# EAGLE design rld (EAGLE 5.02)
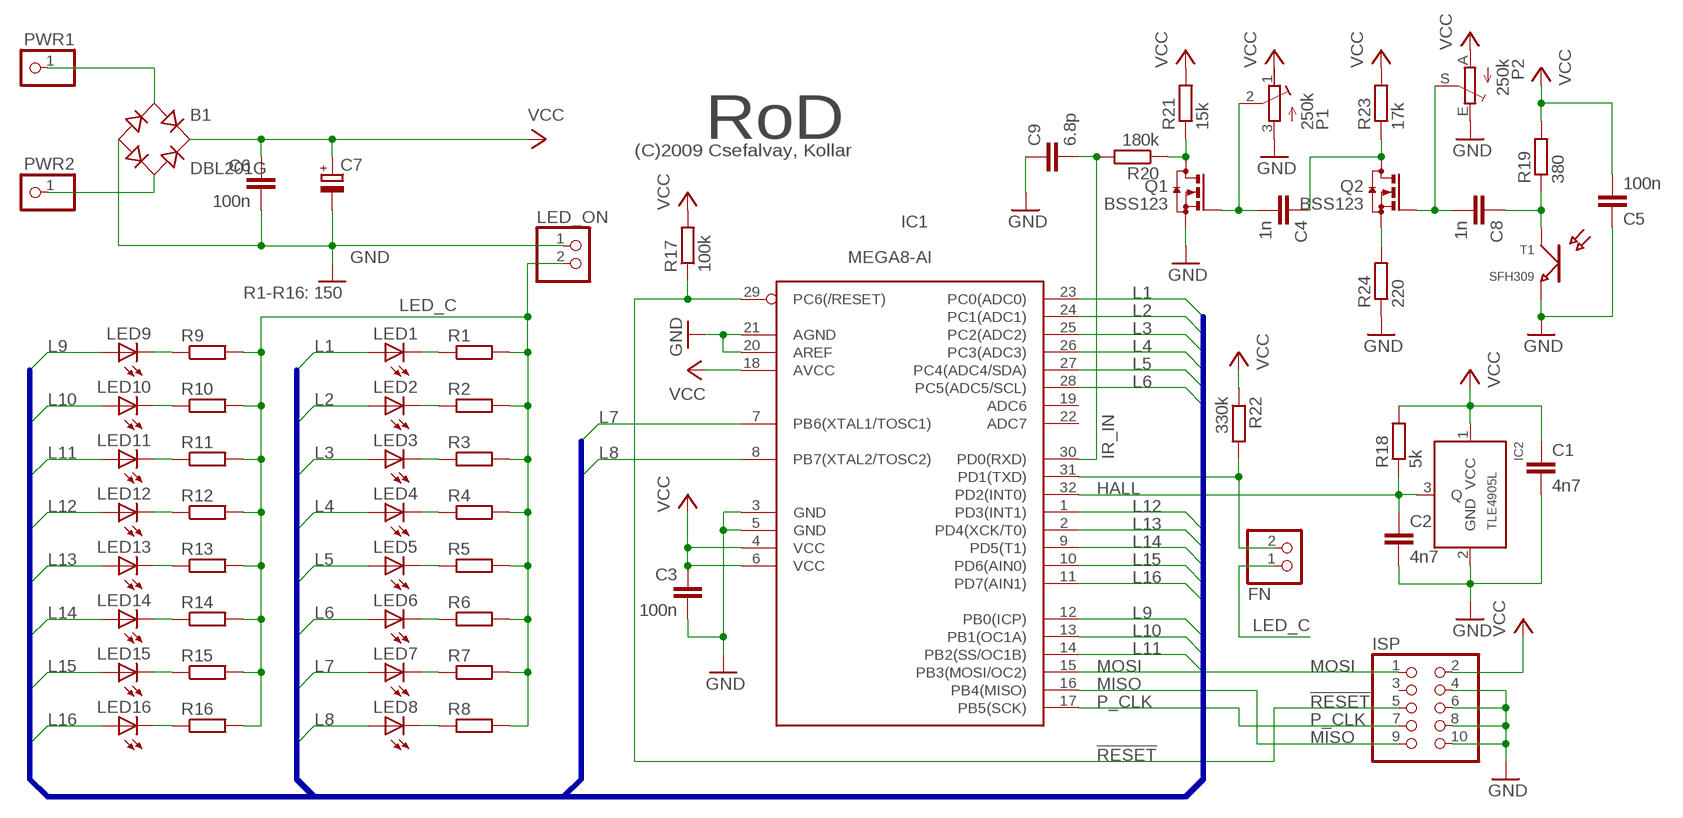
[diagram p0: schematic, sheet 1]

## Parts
B1  DBL201G  [DB]
C1  4n7  C-EUC1206  [C1206]
C2  4n7  C-EUC1206  [C1206]
C3  100n  C-EUC1206  [C1206]
C4  1n  C-EUC1206  [C1206]
C5  100n  C-EUC1206  [C1206]
C6  100n  C-EUC1206  [C1206]
C7  CPOL-EUE2.5-7  [E2,5-7]
C8  1n  C-EUC1206  [C1206]
C9  6.8p  C-EUC1206  [C1206]
FN  PINHD-1X2  [1X02]
IC1  MEGA8-AI  [TQFP32-08]
IC2  TLE4905L  [TO92-]
ISP  PINHD-2X5  [2X05]
LED1  LEDCHIPLED_1206  [CHIPLED_1206]
LED2  LEDCHIPLED_1206  [CHIPLED_1206]
LED3  LEDCHIPLED_1206  [CHIPLED_1206]
LED4  LEDCHIPLED_1206  [CHIPLED_1206]
LED5  LEDCHIPLED_1206  [CHIPLED_1206]
LED6  LEDCHIPLED_1206  [CHIPLED_1206]
LED7  LEDCHIPLED_1206  [CHIPLED_1206]
LED8  LEDCHIPLED_1206  [CHIPLED_1206]
LED9  LEDCHIPLED_1206  [CHIPLED_1206]
LED10  LEDCHIPLED_1206  [CHIPLED_1206]
LED11  LEDCHIPLED_1206  [CHIPLED_1206]
LED12  LEDCHIPLED_1206  [CHIPLED_1206]
LED13  LEDCHIPLED_1206  [CHIPLED_1206]
LED14  LEDCHIPLED_1206  [CHIPLED_1206]
LED15  LEDCHIPLED_1206  [CHIPLED_1206]
LED16  LEDCHIPLED_1206  [CHIPLED_1206]
LED_ON  PINHD-1X2  [1X02]
P1  250k  R-TRIMM3006P  [RTRIM3006P]
P2  250k  TRIM_EU-CA6V  [CA6V]
PWR1  PINHD-1X1  [1X01]
PWR2  PINHD-1X1  [1X01]
Q1  BSS123  [SOT23]
Q2  BSS123  [SOT23]
R1  R-EU_R1206  [R1206]
R2  R-EU_R1206  [R1206]
R3  R-EU_R1206  [R1206]
R4  R-EU_R1206  [R1206]
R5  R-EU_R1206  [R1206]
R6  R-EU_R1206  [R1206]
R7  R-EU_R1206  [R1206]
R8  R-EU_R1206  [R1206]
R9  R-EU_R1206  [R1206]
R10  R-EU_R1206  [R1206]
R11  R-EU_R1206  [R1206]
R12  R-EU_R1206  [R1206]
R13  R-EU_R1206  [R1206]
R14  R-EU_R1206  [R1206]
R15  R-EU_R1206  [R1206]
R16  R-EU_R1206  [R1206]
R17  100k  R-EU_R1206  [R1206]
R18  5k  R-EU_R1206  [R1206]
R19  380  R-EU_R1206  [R1206]
R20  180k  R-EU_R1206  [R1206]
R21  15k  R-EU_R1206  [R1206]
R22  330k  R-EU_R1206  [R1206]
R23  17k  R-EU_R1206  [R1206]
R24  220  R-EU_R1206  [R1206]
T1  SFH309  [D-2.54]

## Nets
!RESET: IC1.29(PC6(/RESET)) ISP.5 R17.1
GND: B1.- C1.2 C2.2 C3.2 C5.1 C6.2 C7.- C9.1 IC1.3(GND) IC1.5(GND) IC1.20(AREF) IC1.21(AGND) IC2.2(GND) ISP.4 ISP.6 ISP.8 ISP.10 LED_ON.1 P1.3(E) P2.E Q1.2(S) R24.1 T1.E
HALL: C2.1 IC1.32(PD2(INT0)) IC2.3(Q) R18.1
IR_IN: C9.2 IC1.30(PD0(RXD)) R20.2
L1: IC1.23(PC0(ADC0)) LED1.A
L2: IC1.24(PC1(ADC1)) LED2.A
L3: IC1.25(PC2(ADC2)) LED3.A
L4: IC1.26(PC3(ADC3)) LED4.A
L5: IC1.27(PC4(ADC4/SDA)) LED5.A
L6: IC1.28(PC5(ADC5/SCL)) LED6.A
L7: IC1.7(PB6(XTAL1/TOSC1)) LED7.A
L8: IC1.8(PB7(XTAL2/TOSC2)) LED8.A
L9: IC1.12(PB0(ICP)) LED9.A
L10: IC1.13(PB1(OC1A)) LED10.A
L11: IC1.14(PB2(SS/OC1B)) LED11.A
L12: IC1.1(PD3(INT1)) LED12.A
L13: IC1.2(PD4(XCK/T0)) LED13.A
L14: IC1.9(PD5(T1)) LED14.A
L15: IC1.10(PD6(AIN0)) LED15.A
L16: IC1.11(PD7(AIN1)) LED16.A
LED_C: FN.1 LED_ON.2 R1.2 R2.2 R3.2 R4.2 R5.2 R6.2 R7.2 R8.2 R9.2 R10.2 R11.2 R12.2 R13.2 R14.2 R15.2 R16.2
MISO: IC1.16(PB4(MISO)) ISP.9
MOSI: IC1.15(PB3(MOSI/OC2)) ISP.1
N$1: LED10.C R10.1
N$2: LED11.C R11.1
N$3: LED12.C R12.1
N$4: LED13.C R13.1
N$5: LED14.C R14.1
N$6: LED15.C R15.1
N$7: LED16.C R16.1
N$8: LED8.C R8.1
N$9: LED7.C R7.1
N$10: LED6.C R6.1
N$11: LED5.C R5.1
N$12: LED4.C R4.1
N$13: LED3.C R3.1
N$14: LED2.C R2.1
N$15: LED9.C R9.1
N$16: LED1.C R1.1
N$17: C4.2 P1.2(S) Q1.1(G)
N$18: C4.1 Q2.3(D) R23.1
N$19: FN.2 IC1.31(PD1(TXD)) R22.2
N$21: Q2.2(S) R24.2
N$22: C8.2 P2.S Q2.1(G)
N$23: C8.1 R19.1 T1.C
N$24: Q1.3(D) R20.1 R21.1
N$31: B1.AC1 PWR1.1
N$32: B1.AC2 PWR2.1
P_CLK: IC1.17(PB5(SCK)) ISP.7
VCC: B1.+ C1.1 C3.1 C5.2 C6.1 C7.+ IC1.4(VCC) IC1.6(VCC) IC1.18(AVCC) IC2.1(VCC) ISP.2 P1.1(A) P2.A R17.2 R18.2 R19.2 R21.2 R22.1 R23.2
Unconnected: IC1.19(ADC6) IC1.22(ADC7) ISP.3

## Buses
LEDS:L[1..16]

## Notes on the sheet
- RoD
- (C)2009 Csefalvay, Kollar
- R1-R16: 150

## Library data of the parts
B1 = rectifier:DB?*G: Single Phase 1.0 AMP Glass Passivated Bridge Rectifier Taiwan Semiconductor Co.,Ltd. - TSC Source: http://www.taiwansemi.com/TSCbig5/ezcatfiles/cust/img/img/db101g.pdf http://www.ts.com.tw/db/pictures/modules/PDT/PDT060207001/DBLS201G.pdf
C1-C6 C8 C9 = rcl:C-EU: CAPACITOR, European symbol
C7 = rcl:CPOL-EU: POLARIZED CAPACITOR, European symbol
FN LED_ON = pinhead:PINHD-1X2: PIN HEADER
IC1 = atmel-cust:MEGA8: MICROCONTROLLER 8 Kbytes FLASH, 1 kbytes SRAM, 512 bytes EEPROM, USART, 6-channel 10 bit ADC, 2-channel 8 bit ADC Pin compatible with Atmega48, ATMega88, ATMega168 Source: avr.lbr
IC2 = tle4905l:TLE4905L
ISP = pinhead:PINHD-2X5: PIN HEADER
LED1-LED16 = led:LED: LED
P1 = rcl:R-TRIMM: Trimm resistor
P2 = pot:TRIM_EU-: POTENTIOMETER
PWR1 PWR2 = pinhead:PINHD-1X1: PIN HEADER
Q1 Q2 = transistor-small-signal:BSS123: N-CHANNEL MOS FET
R1-R24 = rcl:R-EU_: RESISTOR, European symbol
T1 = photo-transistor:SFH309: Phototransistor

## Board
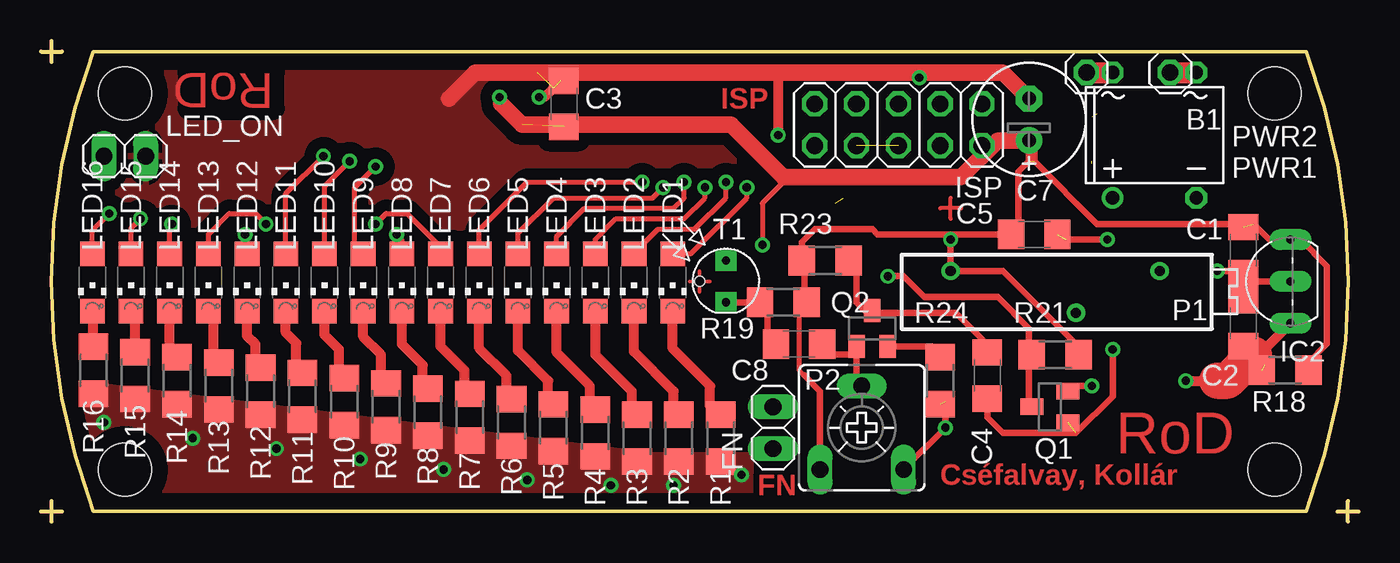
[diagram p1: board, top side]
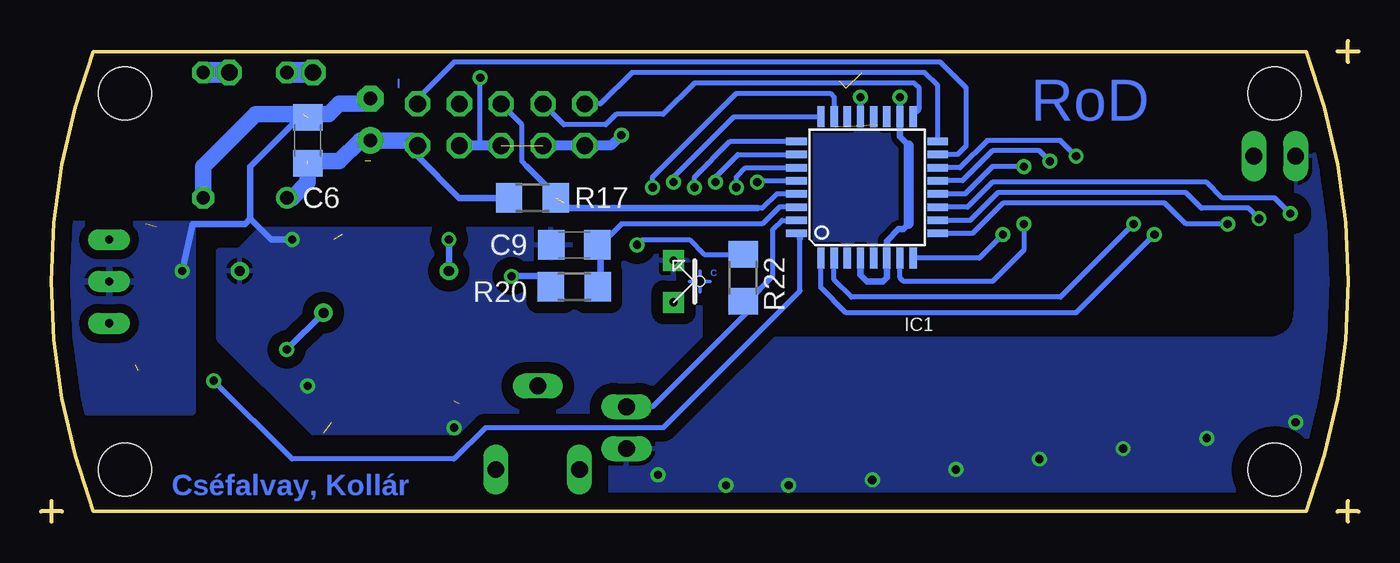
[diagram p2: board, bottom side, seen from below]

Size 80.01 x 29.21 mm. Coordinates in mm from the lower left corner, seen from the top.
Outline: 0,28.57 1.27,28.57
Outline: 0.64,27.94 0.64,29.21
Outline: 0,0.64 1.27,0.64
Outline: 0.64,0 0.64,1.27
Outline: 78.74,0.64 80.01,0.64
Outline: 79.38,0 79.38,1.27
Outline: 76.84,28.57 3.18,28.57 arc42 3.18,0.64 76.84,0.64 arc42 76.84,28.57
Copper layers (1*16): Top 0.035mm / dielectric 1.5mm / Bottom 0.035mm
Design rules "default": minimum track width 10mil, minimum drill 24mil, track to track 8mil, track to pad 8mil, pad to pad 8mil, via to via 8mil, smd to smd 8mil, copper to edge 40mil, drill to drill 8mil, minimum pad ring 10mil, minimum via ring 8mil, stop-mask expansion 4mil, vias tented up to drill 0mil, thermal gap 10mil
Holes 0.6 mm at 40,14.61
Holes 3.2 mm at 5.08,26.04 5.08,3.18 74.93,26.04 74.93,3.18

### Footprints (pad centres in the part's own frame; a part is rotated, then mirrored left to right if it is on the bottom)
DB = drill 0.813 round: + -2.54,-3.81 | drill 0.813 octagon: - 2.54,-3.81; AC1 2.54,3.81; AC2 -2.54,3.81
C1206 = smd 1.6 x 1.8: 1 -1.4,0; 2 1.4,0
E2,5-7 = drill 0.813 pad 1.6 round: + -1.27,0 | drill 0.813 pad 1.6 octagon: - 1.27,0
1X02 = drill 1.016 long: 1 -1.27,0; 2 1.27,0
TQFP32-08 = smd 1.27 x 0.45: 1 -4.293,2.8; 2 -4.293,2; 3 -4.293,1.2; 4 -4.293,0.4; 5 -4.293,-0.4; 6 -4.293,-1.2; 7 -4.293,-2; 8 -4.293,-2.8; 17 4.293,-2.8; 18 4.293,-2; 19 4.293,-1.2; 20 4.293,-0.4; 21 4.293,0.4; 22 4.293,1.2; 23 4.293,2; 24 4.293,2.8 | smd 0.45 x 1.27: 9 -2.8,-4.293; 10 -2,-4.293; 11 -1.2,-4.293; 12 -0.4,-4.293; 13 0.4,-4.293; 14 1.2,-4.293; 15 2,-4.293; 16 2.8,-4.293; 25 2.8,4.293; 26 2,4.293; 27 1.2,4.293; 28 0.4,4.293; 29 -0.4,4.293; 30 -1.2,4.293; 31 -2,4.293; 32 -2.8,4.293
TO92- = drill 0.5 pad 1.27 long: 1 2.54,0; 2 0,0; 3 -2.54,0
2X05 = drill 1.016 octagon: 1 -5.08,-1.27; 2 -5.08,1.27; 3 -2.54,-1.27; 4 -2.54,1.27; 5 0,-1.27; 6 0,1.27; 7 2.54,-1.27; 8 2.54,1.27; 9 5.08,-1.27; 10 5.08,1.27
CHIPLED_1206 = smd 1.5 x 1.5: A 0,-1.75; C 0,1.75
RTRIM3006P = drill 0.61 round: 1 -7.62,1.27; 2 0,-1.27; 3 5.08,1.27
CA6V = drill 1.016 long: A -2.54,-2.54; E 2.54,-2.54; S 0,2.54
1X01 = drill 1.016 octagon: 1 0,0
SOT23 = smd 1 x 1.4: 1 -0.95,-1.1; 2 0.95,-1.1; 3 0,1.1
R1206 = smd 1.6 x 1.803: 1 -1.422,0; 2 1.422,0
D-2.54 = drill 0.5 pad 1.27 square: C -1.27,0; E 1.27,0

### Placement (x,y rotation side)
B1  67.63,23.5 0 top
C1  73.03,16.51 270 top
C2  73.03,12.07 90 top
C3  31.75,25.4 90 top
C4  57.47,8.89 270 top
C5  60.32,17.46 180 top
C6  63.82,23.18 90 bottom
C7  60.01,24.45 90 top
C8  46.04,10.79 0 top
C9  47.62,16.83 0 bottom
FN  44.45,5.71 90 top
IC1  29.84,20.32 90 bottom
IC2  75.88,14.61 90 top
ISP  52.07,24.13 180 top
LED1  38.36,14.54 180 top
LED2  36.01,14.54 180 top
LED3  33.66,14.54 180 top
LED4  31.31,14.54 180 top
LED5  28.96,14.54 180 top
LED6  26.61,14.54 180 top
LED7  24.26,14.54 180 top
LED8  21.91,14.54 180 top
LED9  19.56,14.54 180 top
LED10  17.21,14.54 180 top
LED11  14.86,14.54 180 top
LED12  12.51,14.54 180 top
LED13  10.16,14.54 180 top
LED14  7.81,14.54 180 top
LED15  5.46,14.54 180 top
LED16  3.11,14.54 180 top
LED_ON  5.08,22.23 180 top
P1  62.87,13.97 0 top
P2  49.85,5.71 0 top
PWR1  68.58,27.3 270 top
PWR2  63.5,27.3 270 top
Q1  61.28,6.99 90 top
Q2  50.48,11.75 0 top
R1  41.27,5.08 270 top
R2  38.73,5.08 270 top
R3  36.2,5.08 270 top
R4  33.65,5.4 270 top
R5  31.11,5.71 270 top
R6  28.57,6.03 270 top
R7  26.04,6.35 270 top
R8  23.5,6.67 270 top
R9  20.96,6.99 270 top
R10  18.41,7.3 270 top
R11  15.88,7.62 270 top
R12  13.34,7.94 270 top
R13  10.79,8.26 270 top
R14  8.26,8.57 270 top
R15  5.71,8.89 270 top
R16  3.18,9.21 270 top
R17  50.16,19.68 180 bottom
R18  75.56,9.21 0 top
R19  45.08,13.34 0 top
R20  47.62,14.29 0 bottom
R21  61.59,10.16 0 top
R22  37.37,14.83 270 bottom
R23  47.62,15.88 180 top
R24  54.61,8.57 90 top
T1  41.59,14.61 90 top

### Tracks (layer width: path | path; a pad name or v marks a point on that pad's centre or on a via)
!RESET  (1 unrouted)
  Bottom 0.305: IC1.29 35.32,19.92 36.2,19.05 36.51,19.05 | ISP.5 50.8,24.13 50.8,21.91 50.48,21.59
  Bottom 0.406: 36.51,19.05 47.94,19.05 48.26,19.37 50.48,21.59
GND  (via drill 0.5)  (6 unrouted)
  Top 0.406: C1.2 72.84,15.11 72.71,15.24 v71.44,15.24 | 31.56,26.8 C3.2 | 73.34,14.61 IC2.2 | Q1.2 62.54,8.25 v63.82,8.26 | P2.E v54.93,5.71 54.93,7.3 | v64.77,17.14 62.23,17.14
  Top 0.61: v30.24,25.8 30.61,25.85 31.11,26.35 | 44.77,27.3 v44.77,23.5
  Top 1.016: 24.77,25.72 26.35,27.3 30.16,27.3 44.77,27.3 58.42,27.3 C7.-
  Top 1.422: C1.2 C2.2
  Bottom 0.305: 30.25,25.64 v30.24,25.8 | 53.34,22.86 v53.34,26.99
  Bottom 0.406: IC1.21 30.25,25.64 | v64.77,17.14 66.04,17.14 67.31,18.41 | v71.44,15.24 70.8,18.1 67.63,18.1 67.31,18.41 | 67.31,18.41 67.31,21.59 64.14,24.77
  Bottom 0.61: v44.77,23.5 45.4,22.86 ISP.10 ISP.8 | ISP.6 53.34,22.86 ISP.4
  Bottom 1.016: B1.- 70.17,21.59 66.99,24.77 64.14,24.77 62.55,24.77 61.91,25.4 60.32,25.4 C7.-
  pour Bottom (isolate 0.35): 26.04,24.13 26.04,16.51 33.65,16.51 33.65,24.13
  pour Bottom (isolate 0.7): 40,17.78 40,5.4 63.5,5.4 69.22,11.11 69.22,16.51 67.95,16.51 66.67,17.78
  pour Bottom (isolate 0.55): 70.8,18.1 70.8,6.67 79.06,6.67 79.06,18.1
  pour Top (isolate 0.7): 3.18,28.26 3.18,17.14 40.96,17.14 43.5,19.68 43.5,22.23 40.96,24.77 28.57,24.77 28.57,28.26
HALL  (via drill 0.5)  (1 unrouted)
  Top 0.305: C2.1 73.03,10.79 73.66,10.79
  Top 0.406: R18.1 73.98,9.21
  Top 0.61: 73.66,10.16 C2.1 | v69.53,8.57 71.44,8.57 | 74.3,10.48 IC2.3 | 73.66,10.79 73.66,10.48
  Top 0.813: 73.66,10.48 74.3,10.48 74.3,9.53
  Top 2.184: 71.44,8.57 72.07,8.57 73.66,10.16
  Bottom 0.305: 33.91,17.52 IC1.32 | 33.91,17.2 33.91,14.03 42.23,5.71 53.02,5.71 54.93,3.81 64.77,3.81 v69.53,8.57
  Bottom 0.406: 33.91,17.2 33.91,17.52
IR_IN
  Bottom 0.305: IC1.30 35.17,19.12 36.2,18.1 44.77,18.1 46.04,16.83 | 46.04,14.45 R20.2
  Bottom 0.406: 46.04,14.45 46.04,16.83 C9.2
L1  (via drill 0.5)
  Top 0.305: LED1.A 39.47,16.3 42.86,19.68 v42.86,20.32
  Bottom 0.305: IC1.23 31.85,25.81 32.07,26.04 37.78,26.04 42.86,20.96 v42.86,20.32
L2  (via drill 0.5)
  Top 0.305: LED2.A 36.01,16.33 37.46,17.78 39.69,17.78 41.59,19.68 v41.59,20.64
  Bottom 0.305: IC1.24 37.93,24.61 41.59,20.96 v41.59,20.64
L3  (via drill 0.5)
  Top 0.305: LED3.A 33.66,17.15 34.92,18.41 39.05,18.41 40.32,19.68 v40.32,20.32
  Bottom 0.305: IC1.25 38.16,23.12 40.32,20.96 v40.32,20.32
L4  (via drill 0.5)
  Top 0.305: LED4.A 31.31,17.34 33.02,19.05 38.42,19.05 39.05,19.68 v39.05,20.64
  Bottom 0.305: IC1.26 37.69,22.32 39.05,20.96 v39.05,20.64
L5  (via drill 0.5)
  Top 0.305: LED5.A 28.96,17.53 31.11,19.68 37.15,19.68 v37.78,20.32
  Bottom 0.305: IC1.27 37.22,21.52 37.78,20.96 v37.78,20.32
L6  (via drill 0.5)
  Top 0.305: LED6.A 26.61,17.72 29.53,20.64 v36.51,20.64
  Bottom 0.305: IC1.28 36.28,20.72 v36.51,20.64
L7  (via drill 0.5)
  Top 0.305: LED7.A 24.26,16.7 22.23,18.73 20.96,18.73 v20.32,18.1
  Bottom 0.305: IC1.7 27.84,14.83 27.62,14.61 22.23,14.61 20.32,16.51 v20.32,18.1
L8  (via drill 0.5)
  Top 0.305: LED8.A 21.91,17.14 v21.59,17.46
  Bottom 0.305: IC1.8 23.03,16.03 v21.59,17.46
L9  (via drill 0.5)
  Top 0.305: LED9.A 19.56,16.32 19.05,16.83 19.05,20.32 v20.32,21.59
  Bottom 0.305: IC1.12 23.89,19.92 22.23,21.59 v20.32,21.59
L10  (via drill 0.5)
  Top 0.305: LED10.A 17.21,20.39 v18.73,21.91
  Bottom 0.305: v18.73,21.91 19.37,22.54 22.23,22.54 24.05,20.72 IC1.13
L11  (via drill 0.5)
  Top 0.305: LED11.A 14.86,19.94 v17.14,22.23
  Bottom 0.305: IC1.14 24.2,21.52 22.54,23.18 18.1,23.18 v17.14,22.23
L12  (via drill 0.5)
  Top 0.305: LED12.A 12.51,17.33 v12.38,17.46
  Bottom 0.305: IC1.1 32.64,14.23 31.11,12.7 17.14,12.7 v12.38,17.46
L13  (via drill 0.5)
  Top 0.305: LED13.A 10.16,17.46 11.43,18.73 13.02,18.73 v13.65,18.1
  Bottom 0.305: IC1.2 31.85,14.7 30.8,13.65 18.1,13.65 v13.65,18.1
L14  (via drill 0.5)
  Top 0.305: LED14.A 7.81,17.91 v7.94,18.1
  Bottom 0.305: IC1.9 23.44,17.52 21.59,19.37 11.75,19.37 10.48,18.1 v7.94,18.1
L15  (via drill 0.5)
  Top 0.305: LED15.A 5.46,17.84 v6.03,18.41
  Bottom 0.305: IC1.10 23.59,18.32 21.91,20 10.48,20 9.53,19.05 6.67,19.05 v6.03,18.41
L16  (via drill 0.5)
  Top 0.305: LED16.A 3.11,17.72 v4.13,18.73
  Bottom 0.305: IC1.11 23.74,19.12 22.23,20.64 9.21,20.64 8.26,19.68 5.08,19.68 v4.13,18.73
LED_C  (via drill 0.5)
  other vias: 3.81,6.03 9.21,5.08 14.29,4.45 19.37,3.81 24.45,3.18 29.53,2.54 34.61,2.22 38.42,2.22 42.54,2.86
  pour Top (isolate 0.254, no thermals): 1.9,6.99 3.49,0.64 43.18,0.64 43.18,4.13 37.15,4.13 1.9,8.57
  pour Bottom (isolate 0.7): 1.27,11.11 3.49,1.27 45.4,1.27 45.4,11.11
  pour Bottom (isolate 0.813): 5.4,9.21 0.64,9.21 0.64,24.13 3.81,24.13 3.81,12.7 arc90 5.4,11.11
MISO
  Bottom 0.305: IC1.16 25.55,26.5 26.35,27.3 44.13,27.3 46.04,25.4 ISP.9
MOSI
  Bottom 0.305: IC1.15 24.35,22.32 23.81,22.86 23.81,26.35 25.4,27.94 54.93,27.94 57.15,25.72 ISP.1
N$1
  Top 0.406: R10.1 18.1,8.57
  Top 0.61: LED10.C 17.21,11.36 18.1,10.48 18.1,8.57
N$2
  Top 0.406: R11.1 15.41,9.04 15.5,8.95
  Top 0.61: LED11.C 14.86,11.49 15.5,10.86 15.5,8.95
N$3
  Top 0.406: R12.1 12.87,9.36 13.02,9.53
  Top 0.61: 13.02,9.53 13.02,10.79 12.51,11.3 LED12.C
N$4
  Top 0.406: R13.1 10.33,9.68 10.16,9.84 10.48,9.85
  Top 0.61: 10.48,9.85 10.48,12.38 10.16,12.7 LED13.C
N$5
  Top 0.406: R14.1 7.94,9.84 7.81,9.97
  Top 0.61: 7.81,9.97 LED14.C
N$6
  Top 0.406: 5.71,12.7 5.46,12.77 LED15.C
  Top 0.61: R15.1 5.71,12.7
N$7
  Top 0.406: 3.18,12.7 2.95,12.79 LED16.C
  Top 0.61: R16.1 3.18,12.7
N$8
  Top 0.406: 23.18,7.94 R8.1 23.18,8.26
  Top 0.61: LED8.C 21.91,10.79 23.18,9.53 23.18,8.26
N$9
  Top 0.406: 25.72,7.62 R7.1 25.72,7.94
  Top 0.61: LED7.C 24.26,10.66 25.72,9.21 25.72,7.94
N$10
  Top 0.406: R6.1 28.26,7.62
  Top 0.61: LED6.C 26.61,10.54 28.26,8.89 28.26,7.62
N$11
  Top 0.406: R5.1 30.8,7.3
  Top 0.61: LED5.C 28.96,10.41 30.8,8.57 30.8,7.3
N$12
  Top 0.406: R4.1 33.34,6.67
  Top 0.61: LED4.C 31.31,10.28 33.34,8.26 33.34,6.99 R4.1
N$13
  Top 0.406: R3.1 35.88,6.67
  Top 0.61: LED3.C 33.66,10.15 35.88,7.94 35.88,6.67
N$14
  Top 0.406: R2.1 38.42,6.35
  Top 0.61: LED2.C 36.01,10.34 38.42,7.94 38.42,6.35
N$15
  Top 0.406: R9.1 20.64,8.57
  Top 0.61: LED9.C 19.56,11.24 20.64,10.16 20.64,8.57
N$16
  Top 0.406: R1.1 40.96,6.35
  Top 0.61: LED1.C 38.36,10.53 40.64,8.26 40.64,6.99 R1.1
N$17  (via drill 0.5)  (1 unrouted)
  Top 0.406: C4.2 57.47,6.35 58.42,5.4 62.87,5.4 65.09,7.62 v65.09,10.48
  Bottom 0.406: v65.09,10.48 P1.2
N$18
  Top 0.406: 50.16,12.7 Q2.3 | 50.16,12.7 49.53,13.34 49.53,15.56 R23.1 | 50.16,12.7 55.56,12.7 57.15,11.11 C4.1
N$19
  Bottom 0.305: IC1.31 35.02,18.32 35.56,17.78 35.56,14.92 37.15,13.34 R22.2 37.22,12.63 42.86,6.99 FN.2
N$20
  Bottom 0.2: 40,13.97 40,15.24
N$21
  Top 0.406: R24.2 54.61,10.16 54.12,10.65 Q2.2
N$22
  Top 0.406: C8.2 47.62,10.48 47.94,10.16 49.53,10.16 | Q2.1 49.53,10.33 49.53,10.16 | P2.S 49.53,8.57 49.53,10.16
N$23
  Top 0.406: C8.1 44.45,10.48 44.13,10.79 44.13,11.11 44.13,12.7 R19.1 T1.C
N$24  (via drill 0.5)
  Top 0.305: 60.01,9.84 R21.1
  Top 0.406: Q1.3 60.01,7.16 60.01,9.84 60.01,11.75 58.1,13.65 53.66,13.65 52.39,14.92 v51.43,14.92
  Bottom 0.305: R20.1 49.21,14.92
  Bottom 0.406: 49.21,14.92 v51.43,14.92
N$25
  Top 0.254: 55.88,19.05 54.61,19.05
N$26
  Top 0.254: 55.24,18.41 55.24,19.68
N$28
  Bottom 0.2: 40.64,14.61 39.37,14.61
N$29
  Top 0.2: 40,13.97 40,15.24
N$30
  Top 0.2: 40.64,14.61 39.37,14.61
N$31
  Top 1.27: PWR1.1 B1.AC1
  Bottom 1.27: PWR1.1 B1.AC1
N$32
  Top 1.27: PWR2.1 B1.AC2
  Bottom 1.27: PWR2.1 B1.AC2
P_CLK
  Bottom 0.305: IC1.17 27.05,24.71 26.67,25.08 26.67,26.35 26.99,26.67 40.32,26.67 42.23,24.77 45.08,24.77 45.72,24.13 48.26,24.13 ISP.7
VCC  (via drill 0.5)  (4 unrouted)
  Top 0.305: 46.35,13.34 R19.2 46.04,12.87 46.04,9.21 46.35,8.89 | R23.2 46.35,15.72 | v43.81,16.83 43.81,19.37 45.4,20.96
  Top 0.406: 73.66,18.1 74.61,17.14 IC2.1 76.52,17.14 78.11,15.56 78.11,10.79 76.99,9.68 R18.2 | C7.+ 60.01,21.91 59.37,21.27 59.37,18.1 C5.2 55.56,17.46 | 60.32,22.86 60.32,21.91 64.14,18.1 72.39,18.1 72.71,17.78 73.03,17.78 C1.1 | v27.85,25.8 v27.86,25.8 | P2.A 47.31,7.94 46.35,8.89 | 46.04,15.88 R23.2 46.2,16.99 46.99,17.78 50.48,17.78 50.8,17.46 55.56,17.46 | 55.56,17.46 v55.24,17.14 P1.1 58.42,15.24 63.18,10.48 R21.2 | 46.35,15.72 46.35,13.34
  Top 0.813: v27.86,25.8 27.94,25.4
  Top 1.016: 27.94,25.4 29.21,24.13 41.91,24.13 45.08,20.96 45.4,20.96 55.88,20.96 58.1,23.18 C7.+
  Bottom 0.305: 27.84,25.62 v27.85,25.8 | R22.1 39.75,16.25 40.64,17.14 43.5,17.14 v43.81,16.83
  Bottom 0.406: IC1.4 30.25,15 29.84,14.61 28.89,14.61 28.64,14.85 IC1.6 28.64,17.07 27.94,17.78 27.62,17.78 27.3,18.1 | 27.3,22.86 27.84,23.4 IC1.18 27.84,25.62 | R17.2 54.61,19.68 57.15,22.23 ISP.2 | v55.24,17.14 P1.1
  Bottom 0.61: 27.3,18.1 27.3,22.86
  Bottom 1.016: ISP.2 57.47,23.18 C7.+ 60.64,23.18 61.91,21.91 63.82,21.91 63.82,20.64 64.77,19.68 B1.+
(copper drawn outside any net)
  shapes: Bottom circle x4

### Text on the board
Top: RoD | ISP | RoD | FN | Cséfalvay, Kollár
Bottom: I | RoD | C | Cséfalvay, Kollár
